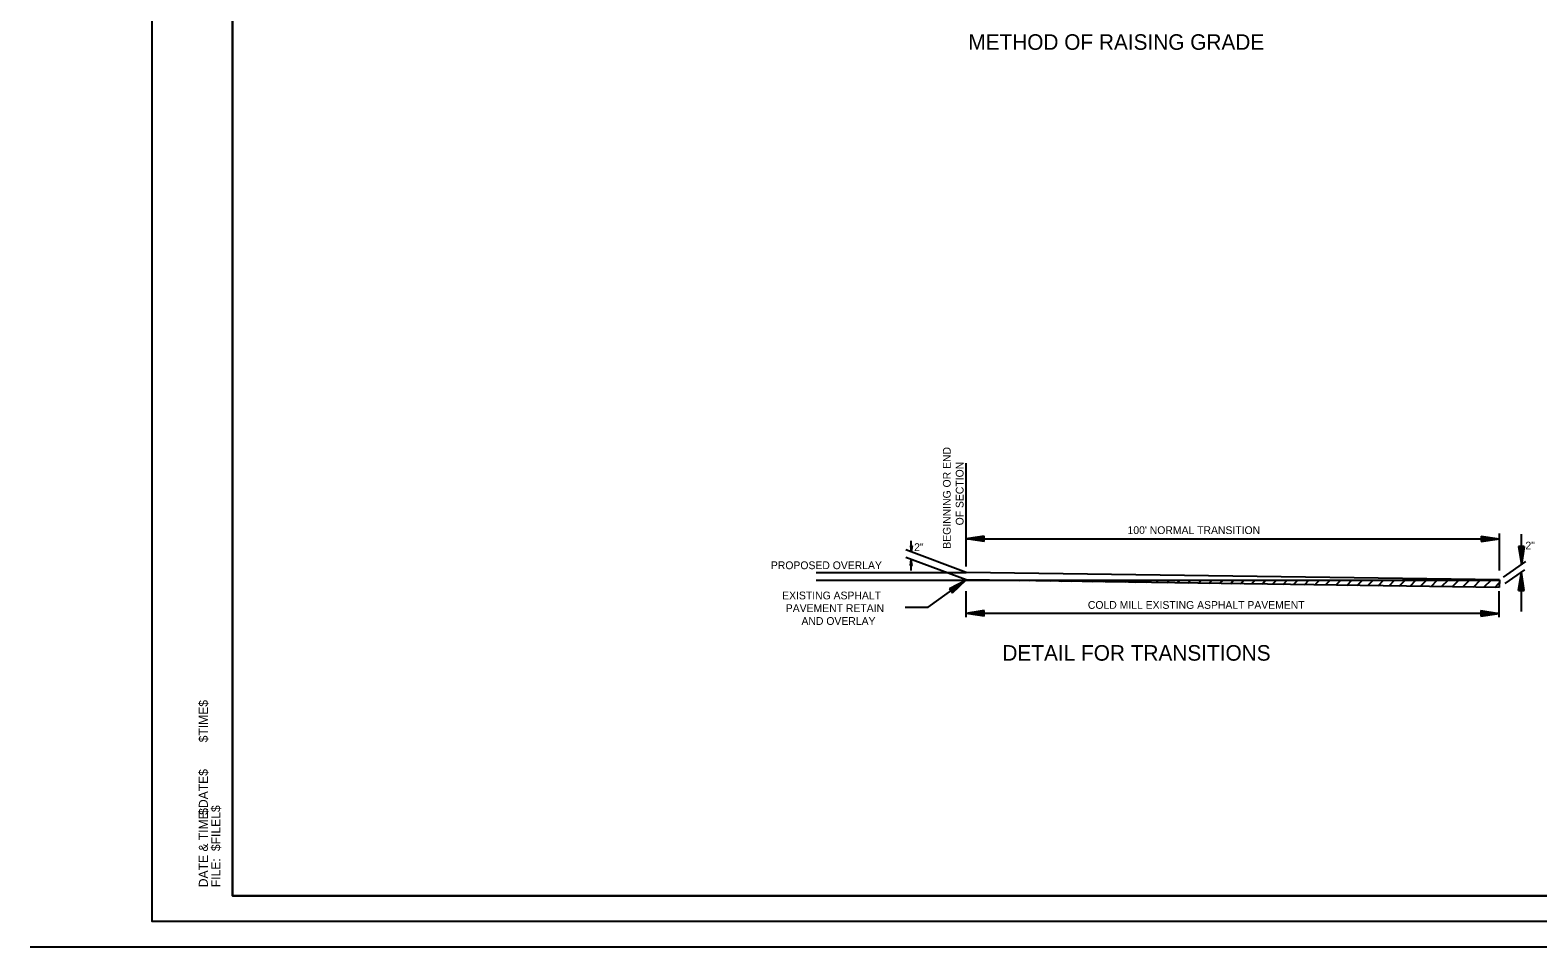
# Model space of a CAD drawing. Extents: x 3575 to 11445, y 9479 to 13278.
# Drawn here: x 3953 to 5116, y 10000 to 10707 of the extents above; entities that cross this region are included whole.
import ezdxf

# ---------------------------------------------------------------- set-up
doc = ezdxf.new("R2010")
doc.units = 0
for name, color, linetype in [('_Drafting 1', 7, 'Continuous'), ('Default', 7, 'Continuous'), ('R_NoPlot', 7, 'Continuous'), ('STAMP_PE_CRAFTON-SIGNATURE', 7, 'Continuous'), ('STAMP_PRELIMINARY', 7, 'Continuous')]:
    doc.layers.add(name, color=color, linetype=linetype)

msp = doc.modelspace()

# ---------------------------------------------------------------- linework, layer by layer
at = {"layer": '_Drafting 1'}
msp.add_lwpolyline([(4109.5, 11066.7), (4109.5, 10039.4), (5690.4, 10039.4), (5690.4, 11002.7), (5474.9, 11002.7), (5474.9, 11001.3), (5458.7, 11001.3), (5458.7, 11017.3), (5279.1, 11017.3), (5279.1, 11066.7)], close=True, dxfattribs=at)
at = {"layer": 'Default'}
for p, q in [((4675.3, 10293.5), (4675.3, 10373.3)), ((4689.4, 10316.9), (4675.3, 10314.8)), ((4689.4, 10316.6), (4677.6, 10314.8)), ((4689.4, 10316.2), (4680.1, 10314.8)), ((4689.4, 10315.9), (4682.4, 10314.8)), ((4689.4, 10315.5), (4684.8, 10314.8)), ((4689.4, 10312.7), (4689.4, 10316.9)), ((5072.7, 10316.9), (5086.8, 10314.8)), ((5072.7, 10316.9), (5072.7, 10312.7)), ((5072.7, 10316.6), (5084.4, 10314.8)), ((5072.7, 10316.2), (5082, 10314.8)), ((5072.7, 10315.8), (5079.7, 10314.8)), ((5072.7, 10315.5), (5077.3, 10314.8)), ((5086.8, 10290.4), (5086.8, 10318.8)), ((5103.7, 10294.8), (5103.7, 10318.4)), ((4675.3, 10288.8), (4628.8, 10306.2)), ((4632.4, 10309.3), (4633.1, 10304.8)), ((4632.4, 10309.3), (4633.1, 10305.5)), ((4633.7, 10309.3), (4632.4, 10309.3)), ((4632.6, 10309.3), (4633.1, 10306.4)), ((4632.6, 10309.3), (4633.1, 10307)), ((4632.8, 10309.3), (4633.1, 10307.9)), ((4632.8, 10309.3), (4633.1, 10308.6)), ((4633.1, 10304.8), (4633.1, 10313.3)), ((4633.7, 10309.3), (4633.1, 10304.8)), ((4633.3, 10309.3), (4633.1, 10307.9)), ((4633.5, 10309.3), (4633.1, 10306.4)), ((4633.5, 10309.3), (4633.1, 10305.5)), ((4633.3, 10309.3), (4633.1, 10307)), ((4633.1, 10309.3), (4633.1, 10308.6)), ((4675.3, 10314.8), (5086.8, 10314.8)), ((4689.4, 10312.7), (4675.3, 10314.8)), ((4689.4, 10313.1), (4677.6, 10314.8)), ((4689.4, 10313.4), (4680.1, 10314.8)), ((4689.4, 10313.8), (4682.4, 10314.8)), ((4689.4, 10314.1), (4684.8, 10314.8)), ((4689.4, 10315.1), (4687.1, 10314.8)), ((4689.4, 10314.5), (4687.1, 10314.8)), ((5072.7, 10315.1), (5074.9, 10314.8)), ((5072.7, 10312.7), (5086.8, 10314.8)), ((5072.7, 10314.1), (5077.3, 10314.8)), ((5072.7, 10313.4), (5082, 10314.8)), ((5072.7, 10313), (5084.4, 10314.8)), ((5072.7, 10313.7), (5079.7, 10314.8)), ((5072.7, 10314.5), (5074.9, 10314.8)), ((5101.6, 10309), (5103.7, 10294.8)), ((5105.8, 10309), (5101.6, 10309)), ((5101.9, 10309), (5103.7, 10297.2)), ((5102.3, 10309), (5103.7, 10299.6)), ((5102.6, 10309), (5103.7, 10302)), ((5103, 10309), (5103.7, 10304.4)), ((5103.4, 10309), (5103.7, 10306.7)), ((5105.8, 10309), (5103.7, 10294.8)), ((5104.3, 10309), (5103.7, 10304.4)), ((5105.1, 10309), (5103.7, 10299.6)), ((5105.5, 10309), (5103.7, 10297.2)), ((5104.7, 10309), (5103.7, 10302)), ((5104, 10309), (5103.7, 10306.7)), ((4675.3, 10283.1), (4628.8, 10300.4)), ((4632.4, 10294.2), (4633.1, 10298.8)), ((4632.4, 10294.2), (4633.1, 10298.2)), ((4632.4, 10294.2), (4633.7, 10294.2)), ((4632.6, 10294.2), (4633.1, 10297.3)), ((4632.6, 10294.2), (4633.1, 10296.6)), ((4632.8, 10294.2), (4633.1, 10295.7)), ((4632.8, 10294.2), (4633.1, 10294.8)), ((4633.7, 10294.2), (4633.1, 10298.8)), ((4633.1, 10290.4), (4633.1, 10298.8)), ((4633.5, 10294.2), (4633.1, 10298.2)), ((4633.5, 10294.2), (4633.1, 10297.3)), ((4633.3, 10294.2), (4633.1, 10296.6)), ((4633.3, 10294.2), (4633.1, 10295.7)), ((4633.1, 10294.2), (4633.1, 10294.8)), ((5089.9, 10285.3), (5107.2, 10297.3)), ((4559.8, 10288.8), (4675.3, 10288.8)), ((4559.8, 10283), (5086.8, 10283)), ((4646, 10262), (4675.3, 10283.1)), ((4662.6, 10276.5), (4675.3, 10283.1)), ((4662.8, 10276.2), (4673.3, 10281.7)), ((4664.9, 10273.4), (4673.3, 10281.7)), ((4665, 10273.1), (4675.3, 10283.1)), ((5086.8, 10283.1), (4675.3, 10288.8)), ((5086.6, 10277.3), (4675.3, 10283.1)), ((4691.5, 10282.8), (4691.7, 10283.1)), ((4699.6, 10282.7), (4699.9, 10283.1)), ((4707.7, 10282.6), (4708.3, 10283.1)), ((4716, 10282.5), (4716.6, 10283.1)), ((4724.1, 10282.4), (4724.8, 10283.1)), ((4732.2, 10282.3), (4733, 10283.1)), ((4740.3, 10282.1), (4741.2, 10283.1)), ((4748.6, 10282), (4749.7, 10283.1)), ((4756.7, 10281.9), (4757.9, 10283.1)), ((4765.1, 10281.8), (4766.1, 10283.1)), ((4773, 10281.7), (4774.3, 10283.1)), ((4781.3, 10281.6), (4782.8, 10283.1)), ((4789.4, 10281.5), (4791, 10283.1)), ((4797.7, 10281.3), (4799.2, 10283.1)), ((4805.6, 10281.2), (4807.6, 10283.1)), ((4813.9, 10281.1), (4815.9, 10283.1)), ((4822, 10281), (4824.1, 10283.1)), ((4830.1, 10280.9), (4832.3, 10283)), ((4838.2, 10280.8), (4840.7, 10283.1)), ((4846.5, 10280.6), (4848.9, 10283.1)), ((4854.6, 10280.5), (4857.2, 10283.1)), ((4862.7, 10280.4), (4865.4, 10283.1)), ((4870.8, 10280.3), (4873.8, 10283.1)), ((4879.2, 10280.2), (4882, 10283.1)), ((4887, 10280.1), (4890.2, 10283.1)), ((4895.4, 10280), (4898.5, 10283.1)), ((4903.7, 10279.8), (4906.7, 10283.1)), ((4911.8, 10279.7), (4915.1, 10283.1)), ((4919.9, 10279.6), (4923.3, 10283.1)), ((4928, 10279.5), (4931.6, 10283.1)), ((4936.4, 10279.4), (4940, 10283.1)), ((4944.5, 10279.3), (4948.2, 10283.1)), ((4952.6, 10279.2), (4956.4, 10283.1)), ((4960.6, 10279), (4964.6, 10283.1)), ((4969, 10278.9), (4973.1, 10283.1)), ((4976.9, 10278.8), (4981.3, 10283.1)), ((4985.2, 10278.7), (4989.5, 10283.1)), ((4993.3, 10278.6), (4997.7, 10283.1)), ((5001.6, 10278.5), (5006, 10283.1)), ((5009.5, 10278.4), (5014.4, 10283.1)), ((5017.8, 10278.2), (5022.6, 10283.1)), ((5026, 10278.2), (5030.8, 10283.1)), ((5034, 10278), (5039.1, 10283.1)), ((5042.1, 10277.9), (5047.5, 10283.1)), ((5050.4, 10277.8), (5055.7, 10283.1)), ((5058.6, 10277.7), (5063.9, 10283.1)), ((5066.7, 10277.5), (5072.1, 10283.1)), ((5074.8, 10277.4), (5080.6, 10283.1)), ((5083.1, 10277.3), (5086.7, 10281)), ((5086.8, 10283.1), (5086.6, 10277.3)), ((5091.2, 10280.4), (5106.4, 10291)), ((5101.6, 10274.9), (5103.7, 10289.1)), ((5101.9, 10274.9), (5103.7, 10286.7)), ((5102.2, 10274.9), (5103.7, 10284.2)), ((5102.6, 10274.9), (5103.7, 10281.9)), ((5103.7, 10258.8), (5103.7, 10289.1)), ((5105.8, 10274.9), (5103.7, 10289.1)), ((5105.4, 10274.9), (5103.7, 10286.7)), ((5105.1, 10274.9), (5103.7, 10284.2)), ((5104.7, 10274.9), (5103.7, 10281.9)), ((4662.6, 10276.5), (4665, 10273.1)), ((4663, 10275.9), (4671.4, 10280.3)), ((4663.2, 10275.6), (4669.5, 10278.9)), ((4663.4, 10275.4), (4667.5, 10277.5)), ((4663.6, 10275.1), (4665.6, 10276.1)), ((4664, 10274.5), (4665.6, 10276.1)), ((4664.2, 10274.2), (4667.5, 10277.5)), ((4664.4, 10273.9), (4669.5, 10278.9)), ((4664.6, 10273.7), (4671.4, 10280.3)), ((4675.3, 10254.4), (4675.3, 10274.4)), ((5086.6, 10254.4), (5086.6, 10274.4)), ((5101.6, 10274.9), (5105.8, 10274.9)), ((5103, 10274.9), (5103.7, 10279.5)), ((5103.3, 10274.9), (5103.7, 10277.2)), ((5104.4, 10274.9), (5103.7, 10279.5)), ((5104, 10274.9), (5103.7, 10277.2)), ((4628.4, 10262), (4646, 10262)), ((4689.4, 10259.4), (4675.3, 10257.3)), ((4679.7, 10257.9), (4675.3, 10257.3)), ((4679.7, 10257.9), (4675.9, 10257.3)), ((4679.7, 10257.7), (4676.8, 10257.3)), ((4679.7, 10257.7), (4677.5, 10257.3)), ((4689.4, 10259.1), (4677.6, 10257.3)), ((4679.7, 10257.5), (4678.4, 10257.3)), ((4679.7, 10257.5), (4679, 10257.3)), ((4679.7, 10256.6), (4679.7, 10257.9)), ((4689.4, 10258.7), (4680.1, 10257.3)), ((4689.4, 10258.4), (4682.4, 10257.3)), ((4689.4, 10258), (4684.8, 10257.3)), ((4689.4, 10257.6), (4687.1, 10257.3)), ((4689.4, 10255.2), (4689.4, 10259.4)), ((5072.5, 10259.4), (5086.6, 10257.3)), ((5072.5, 10259.4), (5072.5, 10255.2)), ((5072.5, 10259.1), (5084.2, 10257.3)), ((5072.5, 10258.7), (5081.8, 10257.3)), ((5072.5, 10258.3), (5079.4, 10257.3)), ((5072.5, 10258), (5077, 10257.3)), ((5072.5, 10257.6), (5074.7, 10257.3)), ((5086.6, 10257.3), (4675.3, 10257.3)), ((4679.7, 10256.6), (4675.3, 10257.3)), ((4689.4, 10255.2), (4675.3, 10257.3)), ((4679.7, 10256.8), (4675.9, 10257.3)), ((4679.7, 10256.8), (4676.8, 10257.3)), ((4679.7, 10257.1), (4677.5, 10257.3)), ((4689.4, 10255.5), (4677.6, 10257.3)), ((4679.7, 10257.1), (4678.4, 10257.3)), ((4679.7, 10257.3), (4679, 10257.3)), ((4689.4, 10255.9), (4680.1, 10257.3)), ((4689.4, 10256.3), (4682.4, 10257.3)), ((4689.4, 10256.6), (4684.8, 10257.3)), ((4689.4, 10257), (4687.1, 10257.3)), ((5072.5, 10255.2), (5086.6, 10257.3)), ((5072.5, 10256.6), (5077, 10257.3)), ((5072.5, 10255.9), (5081.8, 10257.3)), ((5072.5, 10255.5), (5084.2, 10257.3)), ((5072.5, 10256.2), (5079.4, 10257.3)), ((5072.5, 10256.9), (5074.7, 10257.3))]:
    msp.add_line(p, q, dxfattribs=at)
at = {"layer": 'R_NoPlot'}
msp.add_lwpolyline([(4047.5, 11086.2), (5714.2, 11086.2), (5714.2, 10019.5), (4047.5, 10019.5)], close=True, dxfattribs=at)
at = {"layer": 'STAMP_PRELIMINARY'}
for p, q in [((4109.5, 10039.4), (4109.5, 11066.7)), ((5690.4, 10039.4), (4109.5, 10039.4)), ((3953.4, 10000), (5713.4, 10000))]:
    msp.add_line(p, q, dxfattribs=at)

# ---------------------------------------------------------------- texts
at = {"layer": 'Default'}
for s, height, rotation, p in [('BEGINNING OR END', 6, 90, (4663.5, 10307.2)), ('OF SECTION', 6, 90, (4673.4, 10325.2)), ('2"', 6, 360, (4635.3, 10305.4)), ('$TIME$', 6.98, 90, (4090.5, 10157.8)), ('$DATE$', 6.98, 90, (4090.5, 10101.9)), ('DATE & TIME:', 6.984, 90, (4090.5, 10046)), ('$FILEL$', 6.98, 90, (4100.1, 10073.9)), ('FILE: ', 6.98, 90, (4100.1, 10046))]:
    msp.add_text(s, height=height, rotation=rotation, dxfattribs=at).set_placement(p)
for s, height, p in [("100' NORMAL TRANSITION", 6, (4799.9, 10318.5)), ('2"', 6, (5106.8, 10306.6)), ('PROPOSED OVERLAY', 6, (4524.8, 10291.4)), ('EXISTING ASPHALT', 6, (4533.5, 10268.1)), ('PAVEMENT RETAIN', 6, (4536.3, 10258.3)), ('COLD MILL EXISTING ASPHALT PAVEMENT', 6, (4769.3, 10260.8)), ('AND OVERLAY', 6, (4548.4, 10248.4)), ('DETAIL FOR TRANSITIONS', 12, (4703.4, 10220.8))]:
    msp.add_text(s, height=height, dxfattribs=at).set_placement(p)
at = {"layer": 'STAMP_PE_CRAFTON-SIGNATURE'}
msp.add_text('METHOD OF RAISING GRADE', height=12, dxfattribs=at).set_placement((4677.1, 10692.1))

doc.saveas('drawing.dxf')
